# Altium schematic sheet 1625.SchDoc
size A2
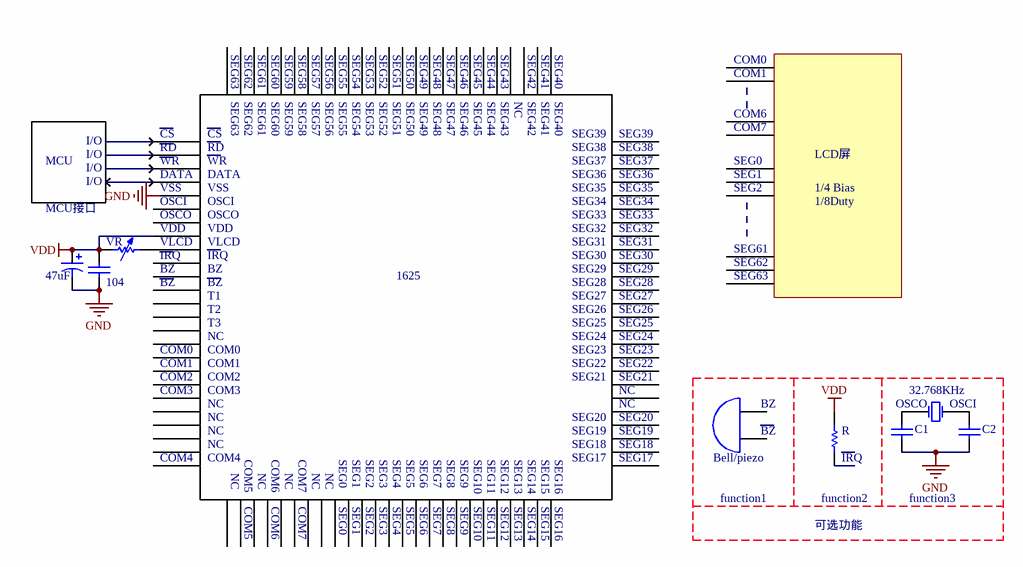
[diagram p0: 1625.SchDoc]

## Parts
(Parts that share a designator on the sheet are numbered #1, #2 ... from top to bottom, then left to right.)
C1  Cap  [RAD-0.3]  (value not drawn)
C2  Cap  [RAD-0.3]  (value not drawn)
C?#1  value 47uF  [RB7.6-15]  (hidden comment: Cap Pol1)
C?#2  value 104  [RAD-0.3]  (hidden comment: Cap)
LS?  Bell/piezo  [PIN2]
R  Res1  [AXIAL-0.3]  (value not drawn)
VR  Res Adj1  [AXIAL-0.7]  (value not drawn)
Y?  32.768KHz  [R38]

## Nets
GND: C1.1 C2.2 C?#1.2 C?#2.1
VDD: C?#1.1 C?#2.2 R.1 VR.1
NetC1_2: C1.2 Y?.1(OSC1)
NetC2_1: C2.1 Y?.2(OSC2)

Not connected (* = marked no-connect by the designer): LS? 1(A) 2(B); R 2; VR 2

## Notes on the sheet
- SEG63
- SEG62
- SEG61
- SEG60
- SEG59
- SEG58
- SEG57
- SEG56
- SEG55
- SEG54
- SEG53
- SEG52
- SEG51
- SEG50
- SEG49
- SEG48
- SEG47
- SEG46
- SEG45
- SEG44
- SEG43
- NC
- SEG42
- SEG41
- SEG40
- COM0
- COM1
- MCU
- I/O
- RD
- WR
- CS
- SEG38
- SEG39
- SEG37
- COM6
- COM7
- SEG0
- LCD屏
- MCU接口
- DATA
- VSS
- (near VR) VDD
- (near VR) OSCI
- (near VR) OSCO
- VDD
- OSCI
- OSCO
- SEG33
- SEG32
- SEG34
- SEG35
- SEG36
- SEG2
- SEG1
- 1/4 Bias
- 1/8Duty
- (near VR) VLCD
- (near VR) IRQ
- (near VR) BZ
- VLCD
- IRQ
- BZ
- T1
- 1625
- SEG30
- SEG28
- SEG27
- SEG31
- SEG29
- T2
- T3
- SEG26
- SEG25
- SEG23
- SEG24
- SEG22
- COM2
- COM3
- SEG21
- SEG19
- SEG20
- (near LS?) BZ
- COM4
- COM5
- SEG3
- SEG4
- SEG5
- SEG6
- SEG7
- SEG8
- SEG9
- SEG10
- SEG11
- SEG12
- SEG13
- SEG14
- SEG15
- SEG16
- SEG18
- SEG17
- function1
- function2
- (near R) IRQ
- function3
- 可选功能
- Labels drawn without touching a wire or pin: GND

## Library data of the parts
C1 C2 = Cap: Capacitor; Value: 104
C?#1 = Cap Pol1: Polarized Capacitor (Radial)
C?#2 = Cap: Capacitor
LS? = Bell: Electrical Bell
R = Res1: Resistor; Value: 1K
VR = Res Adj1: Variable Resistor; Value: 1K; Set Position: 0.5
Y? = XTAL: Crystal Oscillator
